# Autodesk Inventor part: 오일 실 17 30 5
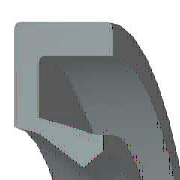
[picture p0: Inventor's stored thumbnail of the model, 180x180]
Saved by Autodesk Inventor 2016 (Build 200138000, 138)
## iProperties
Created: 2012-02
Part Number: 오일 실 17 30 5
Material: 고무
Description: 오일 실 - 스프링 장착, 비스프링, 고무 덮개 G
Document SubType Name: Modeling
Standard: JIS B 2402
Designer: mduedu
Standards Organization: JIS
Language: ko-KR
Size Designation: 17 30 5 A
Categories: <MemberInstance><Categories><Category DisplayName="샤프트 부품" InternalName="7f7aeb1f-a693-4053-b835-cee3144e0d98" Mnemonic="SHFT"><Category DisplayName="실링" Intern
Density: 0.93 g/cm^3
Appearance: 고무 - 검은색 - 버전 1.1
Mass: 1.22959 g
Surface Area: 18.6191 cm^2
Volume: 1.32214 cm^3
IsCustomPart: 1
Author: mduedu
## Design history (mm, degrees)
fillet "모깎기2" dims "d41" = 0.5
fillet "모깎기3" dims "d42" = 0.5
body "Solid1"
revolve "회전1" stored, may be unused: angle "d29" = 360 deg
fillet "모깎기1" dims "d34" = 0.25 (= 0.05 x b)
sketch "스케치2"
  geometry: L1 (9.58, -3.438)-(9.905, -5); L2 (9.147, -3.282)-(9.58, -3.438); L3 (8.5, -1.72)-(9.147, -3.282); L4 (9.682, -1.22)-(8.5, -1.72); L5 (10.811, -3.75)-(9.682, -1.22); L6 (12.111, -3.75)-(10.811, -3.75); L7 (13.556, -1.25)-(12.111, -3.75); L8 (13.556, 0)-(13.556, -1.25); L9 (15, 0)-(13.556, 0); L10 (15, -5)-(15, 0); L11 (9.905, -5)-(15, -5); L12 (0, -9.6)-(0, 1.6) reference; L13 (28, 0)-(14, 0) reference
  constraints: 22 end point, 3 horizontal, 2 vertical
  dimensions: "d2" = 5 distance of L10.start L9.start (= b); "d4" = 1.25 vertical distance of L5.start L1.end (= 0.25 x b); "d6" = 1.44444 distance of L9.start L8.start (= 0.111111 x dd - 0.111111 x Diam); "d8" = 1.25 distance of L8.start L7.start (= 0.25 x b); "d10" = 1.44444 horizontal distance of L7.start L6.start (= 0.111111 x dd - 0.111111 x Diam); "d12" = 1.21951 vertical distance of L9.start L4.start (= 0.243902 x b); "d14" = 1.18182 horizontal distance of L4.start L3.start (= 0.0909091 x dd - 0.0909091 x Diam); "d16" = 0.5 vertical distance of L4.start L3.start (= 0.1 x b); "d18" = 1.3 distance of L6.start L5.start (= 0.1 x dd - 0.1 x Diam); "d20" = 1.5625 vertical distance of L3.start L2.start (= 0.3125 x b); "d22" = 0.64677 horizontal distance of L3.start L2.start (= 0.0497512 x dd - 0.0497512 x Diam); "d24" = 0.325 horizontal distance of L1.start L1.end (= 0.025 x dd - 0.025 x Diam); "d26" = 1.5625 vertical distance of L1.start L1.end (= 0.3125 x b); "d28" = 0.43333 horizontal distance of L2.start L1.start (= 0.0333333 x dd - 0.0333333 x Diam); "d35" = 0 distance between parallel lines of L13 L9; "d36" = 15 distance between parallel lines of L12 L10 (= 0.5 x dd); "d37" = 8.5 distance from line of L12 L3.start (= 0.5 x Diam)
other parameters: "Diam" = 17 [user parameter; used in 8 equation terms], "b" = 5 [user parameter; used in 8 equation terms], "d1" = 8 (derived), "d3" = 2 (derived), "d5" = 2.22222 (derived), "d7" = 2 (derived), "d9" = 2.22222 (derived), "d11" = 1.95122 (derived), "d13" = 1.81818 (derived), "d15" = 0.8 (derived), "d17" = 2 (derived), "d19" = 2.5 (derived), "d21" = 0.99502 (derived), "d23" = 0.5 (derived), "d25" = 2.5 (derived), "d27" = 0.66667 (derived), "d38" = 0
